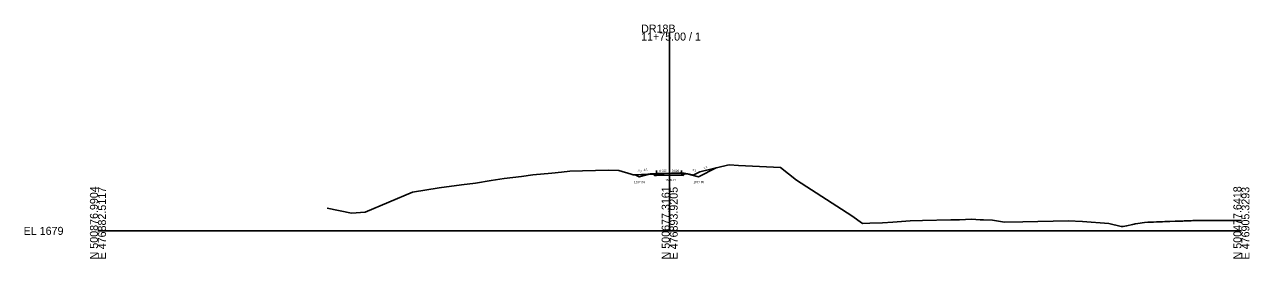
# Model space of a CAD drawing. Extents: x -26 to 403, y -10 to 2578.
# Drawn here: x -25.7 to 402.8, y 1990.3 to 2072.3 of the extents above; entities that cross this region are included whole.
import ezdxf

# ---------------------------------------------------------------- set-up
doc = ezdxf.new("R2010")
doc.units = 0
for name, color, linetype in [('Exist Cross Section Cell', 7, 'Continuous'), ('Exist XS Center Line Elevation Label', 7, 'Continuous'), ('Exist XS Ground Line', 7, 'Continuous'), ('Prop XS Ditch Slope Text', 7, 'Continuous'), ('Prop XS Ditch Standard Text', 7, 'Continuous'), ('Prop XS Earthwork Shape', 7, 'Continuous'), ('Prop XS EOT Tick Mark', 7, 'Continuous'), ('Prop XS Finish Grade', 7, 'Continuous'), ('Prop XS Finish Grade Earthwork', 7, 'Continuous'), ('Prop XS Finish Grade Pavement', 7, 'Continuous'), ('Prop XS Hydro Typical Ditch Data', 7, 'Continuous'), ('Prop XS Pvmt Edge Slope', 7, 'Continuous'), ('Prop XS SE Text', 7, 'Continuous'), ('Prop XS Shoulder Borrow Shape', 7, 'Continuous'), ('Prop XS Side Slope Text', 7, 'Continuous'), ('Prop XS Subgrade Earthwork', 7, 'Continuous')]:
    doc.layers.add(name, color=color, linetype=linetype)

msp = doc.modelspace()

# ---------------------------------------------------------------- linework, layer by layer
at = {"layer": 'Exist Cross Section Cell'}
for p, q in [((200, 2000), (200, 2069.44)), ((0, 2000), (200, 2000)), ((200, 2000), (400, 2000))]:
    msp.add_line(p, q, dxfattribs=at)
at = {"layer": 'Exist XS Ground Line'}
msp.add_lwpolyline([(80.24, 2007.91), (88.72, 2006.15), (93.46, 2006.51), (110.09, 2013.58), (119.34, 2015.04), (127.23, 2016.1), (132.09, 2016.73), (137.53, 2017.62), (142.1, 2018.31), (148.16, 2019.06), (152.12, 2019.58), (158.79, 2020.25), (162.14, 2020.61), (165.13, 2020.86), (178.43, 2021.27), (182.22, 2021.15), (186.51, 2019.87), (187.28, 2019.64), (187.91, 2019.67), (194.54, 2019.92), (195.23, 2019.97), (198.08, 2020.02), (200, 2020.14), (200.7, 2020.19), (203.75, 2020.29), (205.07, 2020.24), (206.92, 2019.88), (207.91, 2019.62), (208.27, 2019.53), (210.57, 2020.67), (220.23, 2022.97), (220.96, 2023.15), (224.07, 2022.94), (238.73, 2022.22), (244.33, 2017.73), (263.74, 2005.21), (267.42, 2002.57), (269.99, 2002.65), (274.48, 2002.77), (278.1, 2003.02), (284.16, 2003.5), (288.42, 2003.66), (298.4, 2003.81), (301.39, 2003.85), (305.6, 2004.12), (308.64, 2003.9), (309.75, 2003.86), (312.95, 2003.73), (317.14, 2003.09), (323.55, 2003.21), (339.42, 2003.52), (344.44, 2003.23), (353.65, 2002.57), (357.93, 2001.57), (358.55, 2001.48), (359.89, 2001.79), (361.93, 2002.21), (362.54, 2002.37), (362.89, 2002.43), (363.81, 2002.58), (366.15, 2002.98), (367.26, 2003.02), (367.58, 2003.03), (368.63, 2003.07), (369.28, 2003.1), (370.28, 2003.13), (371.56, 2003.17), (372.46, 2003.2), (373.26, 2003.23), (374.96, 2003.29), (376.84, 2003.36), (377.43, 2003.38), (379.57, 2003.45), (379.97, 2003.46), (380.32, 2003.48), (382.46, 2003.56), (383.07, 2003.59), (384.32, 2003.64), (384.7, 2003.65), (385.11, 2003.66), (387.48, 2003.67), (390.12, 2003.65), (392.45, 2003.63), (392.76, 2003.63), (394.94, 2003.6), (395.41, 2003.6), (397.44, 2003.58), (399.25, 2003.57), (400, 2003.57)], dxfattribs=at)
at = {"layer": 'Prop XS Earthwork Shape'}
for points in [[(189.35, 2018.94), (187.89, 2019.67), (187.91, 2019.67), (193.03, 2019.86)], [(194.09, 2020), (193.35, 2019.94), (193.03, 2019.86), (194.18, 2019.9)], [(204.09, 2019.45), (200, 2019.53), (195.35, 2019.43), (194.67, 2019.42), (194.18, 2019.9), (194.54, 2019.92), (195.23, 2019.97), (198.08, 2020.02), (200, 2020.14), (200.7, 2020.19), (203.75, 2020.29), (205.07, 2020.24), (206.92, 2019.88), (207.91, 2019.62), (208.27, 2019.53), (210.57, 2020.67), (216.23, 2022.02), (210.09, 2018.95), (206.09, 2019.95), (205.35, 2020.01), (204.77, 2019.43)]]:
    msp.add_lwpolyline(points, close=True, dxfattribs=at)
at = {"layer": 'Prop XS EOT Tick Mark'}
for p, q in [((195.35, 2020.1), (195.35, 2021.1)), ((204.09, 2020.11), (204.09, 2021.11))]:
    msp.add_line(p, q, dxfattribs=at)
at = {"layer": 'Prop XS Finish Grade'}
for p, q in [((195.35, 2020.1), (194.09, 2020)), ((204.09, 2020.11), (205.35, 2020.01))]:
    msp.add_line(p, q, dxfattribs=at)
at = {"layer": 'Prop XS Finish Grade Earthwork'}
for p, q in [((189.35, 2018.94), (187.89, 2019.67)), ((193.35, 2019.94), (189.35, 2018.94)), ((194.09, 2020), (193.35, 2019.94)), ((205.35, 2020.01), (206.09, 2019.95)), ((206.09, 2019.95), (210.09, 2018.95)), ((210.09, 2018.95), (216.23, 2022.02))]:
    msp.add_line(p, q, dxfattribs=at)
at = {"layer": 'Prop XS Finish Grade Pavement'}
for p, q in [((195.35, 2020.1), (200, 2020.19)), ((200, 2020.19), (204.09, 2020.11))]:
    msp.add_line(p, q, dxfattribs=at)
at = {"layer": 'Prop XS Hydro Typical Ditch Data'}
for p, q in [((189.35, 2018.94), (187.89, 2019.67)), ((193.35, 2019.94), (189.35, 2018.94))]:
    msp.add_line(p, q, dxfattribs=at)
at = {"layer": 'Prop XS Pvmt Edge Slope'}
for p, q in [((195.35, 2020.1), (194.67, 2019.42)), ((204.09, 2020.11), (204.77, 2019.43))]:
    msp.add_line(p, q, dxfattribs=at)
at = {"layer": 'Prop XS Shoulder Borrow Shape'}
for points in [[(195.35, 2020.1), (194.67, 2019.42), (194.09, 2020)], [(204.77, 2019.43), (205.35, 2020.01), (204.09, 2020.11)]]:
    msp.add_lwpolyline(points, close=True, dxfattribs=at)
at = {"layer": 'Prop XS Subgrade Earthwork'}
for p, q in [((194.67, 2019.42), (194.09, 2020)), ((195.35, 2019.43), (194.67, 2019.42)), ((200, 2019.53), (195.35, 2019.43)), ((204.09, 2019.45), (200, 2019.53)), ((204.09, 2019.45), (204.77, 2019.43)), ((204.77, 2019.43), (205.35, 2020.01))]:
    msp.add_line(p, q, dxfattribs=at)

# ---------------------------------------------------------------- texts
at = {"layer": 'Exist Cross Section Cell'}
for s, p in [('DR18B', (190, 2069.44)), ('11+75.00 / 1', (190, 2066.64)), ('EL 1679', (-26, 1998.6))]:
    msp.add_text(s, height=2.8, dxfattribs=at).set_placement(p)
for s, p in [('N 500876.9904', (0, 1990)), ('E 476882.5117', (2.8, 1990)), ('N 500677.3161', (200, 1990)), ('E 476893.9205', (202.8, 1990)), ('N 500477.6418', (400, 1990)), ('E 476905.3293', (402.8, 1990))]:
    msp.add_text(s, height=2.8, rotation=90, dxfattribs=at).set_placement(p)
at = {"layer": 'Exist XS Center Line Elevation Label'}
msp.add_text('1699.17', height=0.75, dxfattribs=at).set_placement((198.46, 2017.42))
at = {"layer": 'Prop XS Ditch Slope Text'}
for rotation, p in [(14.0355, (190.98, 2020.9)), (345.9687, (207.88, 2021.05))]:
    msp.add_text('4:1', height=0.75, rotation=rotation, dxfattribs=at).set_placement(p)
at = {"layer": 'Prop XS Ditch Standard Text'}
for s, p in [('1697.94', (187.54, 2016.69)), ('1697.95', (208.29, 2016.7))]:
    msp.add_text(s, height=0.75, dxfattribs=at).set_placement(p)
at = {"layer": 'Prop XS SE Text'}
for rotation, p in [(1.1458, (196.36, 2020.62)), (358.8542, (200.73, 2020.68))]:
    msp.add_text('0.020', height=0.75, rotation=rotation, dxfattribs=at).set_placement(p)
at = {"layer": 'Prop XS Side Slope Text'}
for rotation, p in [(26.5567, (211.96, 2021.56)), (333.4362, (188.76, 2020.91))]:
    msp.add_text('2:1', height=0.75, rotation=rotation, dxfattribs=at).set_placement(p)

doc.saveas('drawing.dxf')
